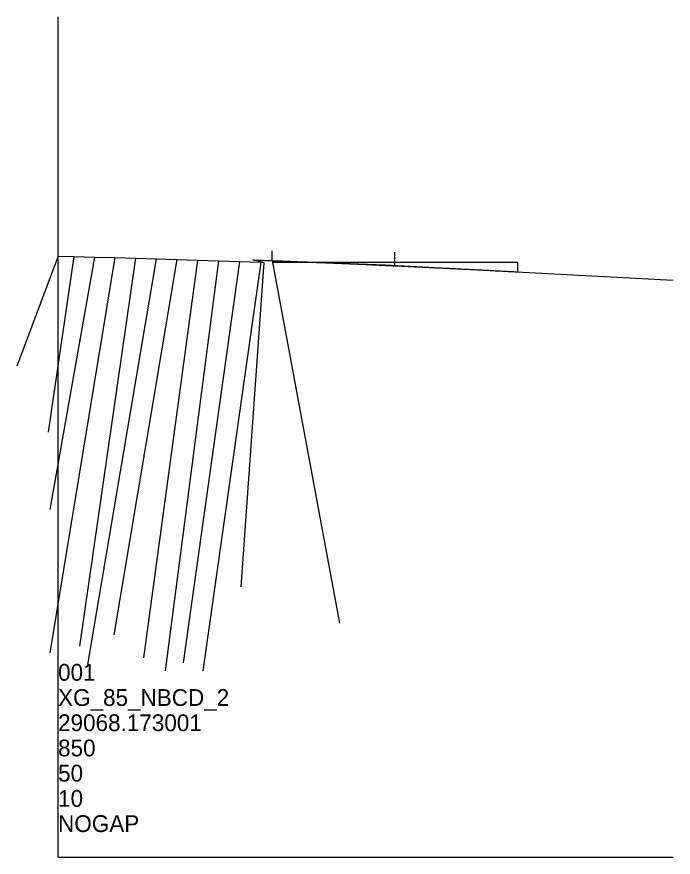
# Model space of a CAD drawing. Extents: x -26 to 1615432, y -20 to 1281970.
# Drawn here: x 176487 to 177268, y 177863 to 178863 of the extents above; entities that cross this region are included whole.
import ezdxf

# ---------------------------------------------------------------- set-up
doc = ezdxf.new("R2010")
doc.units = 0
doc.layers.add('RD_GPK_Profile_Cell', color=7, linetype='Continuous')
doc.layers.add('RD_PD_EarthShd', color=7, linetype='Continuous')

msp = doc.modelspace()

# ---------------------------------------------------------------- linework, layer by layer
at = {"layer": 'RD_GPK_Profile_Cell'}
for q in [(176535.7, 178863), (177267.5, 177863), (176535.7, 177863)]:
    msp.add_line((176535.7, 177863), q, dxfattribs=at)
at = {"layer": 'RD_PD_EarthShd'}
for p, q in [((176790.6, 178572.9), (176790.6, 178584.6)), ((176936.5, 178567.4), (176936.5, 178582.9)), ((176535.7, 178578.3), (176486.6, 178447.3)), ((176554.4, 178577.9), (176523.9, 178368.9)), ((176578.9, 178577.2), (176525.8, 178276.8)), ((176603.4, 178576.6), (176525.8, 178106.2)), ((176627.8, 178575.9), (176561.1, 178114)), ((176652.3, 178575.2), (176570.9, 178092.4)), ((176676.9, 178574.4), (176602.2, 178127.7)), ((176701.6, 178573.6), (176637.5, 178100.3)), ((176726.6, 178572.8), (176663, 178084.6)), ((176751.7, 178571.9), (176684.5, 178094.4)), ((176776.8, 178571), (176708, 178084.6)), ((176780.6, 178570.8), (176753.1, 178184.6)), ((176790.6, 178572.9), (176870.7, 178141.5)), ((176790.6, 178571.2), (177082.5, 178571.2)), ((177082.5, 178559.5), (177082.5, 178571.2))]:
    msp.add_line(p, q, dxfattribs=at)
msp.add_lwpolyline([(176535.7, 178578.3), (176554.4, 178577.9), (176578.9, 178577.2), (176603.4, 178576.6), (176627.8, 178575.9), (176652.3, 178575.2), (176676.9, 178574.4), (176701.6, 178573.6), (176726.6, 178572.8), (176751.7, 178571.9), (176776.8, 178571), (176780.6, 178570.8), (176767.5, 178573.7), (176925, 178568), (177267.5, 178549.5)], dxfattribs=at)
msp.add_spline([(176767.5, 178573.7), (176770.7, 178573.6), (176773.8, 178573.5), (176777, 178573.4), (176780.1, 178573.3), (176783.3, 178573.2), (176786.4, 178573.1), (176789.6, 178572.9), (176792.7, 178572.8), (176795.9, 178572.7), (176799, 178572.6), (176802.2, 178572.5), (176805.3, 178572.3), (176808.5, 178572.2), (176811.6, 178572.1), (176814.8, 178572), (176817.9, 178571.8), (176821.1, 178571.7), (176824.2, 178571.6), (176827.4, 178571.5), (176830.5, 178571.4), (176833.7, 178571.2), (176836.8, 178571.1), (176840, 178571), (176843.1, 178570.8), (176846.3, 178570.7), (176849.4, 178570.6), (176852.6, 178570.5), (176855.7, 178570.3), (176858.9, 178570.2), (176862, 178570.1), (176865.2, 178569.9), (176868.3, 178569.8), (176871.5, 178569.7), (176874.6, 178569.5), (176877.8, 178569.4), (176880.9, 178569.3), (176884.1, 178569.1), (176887.2, 178569), (176890.4, 178568.9), (176893.5, 178568.7), (176896.7, 178568.6), (176899.8, 178568.5), (176903, 178568.3), (176906.1, 178568.2), (176909.3, 178568), (176912.4, 178567.9), (176915.6, 178567.8), (176918.7, 178567.6), (176921.9, 178567.5), (176925, 178567.3), (176928.2, 178567.2), (176931.3, 178567.1), (176934.5, 178566.9), (176937.6, 178566.8), (176940.8, 178566.6), (176943.9, 178566.5), (176947.1, 178566.3), (176950.2, 178566.2), (176953.4, 178566), (176956.5, 178565.9), (176959.7, 178565.7), (176962.8, 178565.6), (176966, 178565.4), (176969.1, 178565.3), (176972.3, 178565.1), (176975.4, 178565), (176978.6, 178564.8), (176981.7, 178564.7), (176984.9, 178564.5), (176988, 178564.4), (176991.2, 178564.2), (176994.3, 178564.1), (176997.5, 178563.9), (177000.6, 178563.8), (177003.8, 178563.6), (177006.9, 178563.5), (177010.1, 178563.3), (177013.2, 178563.1), (177016.4, 178563), (177019.5, 178562.8), (177022.7, 178562.7), (177025.8, 178562.5), (177029, 178562.3), (177032.1, 178562.2), (177035.3, 178562), (177038.4, 178561.9), (177041.6, 178561.7), (177044.7, 178561.5), (177047.9, 178561.4), (177051, 178561.2), (177054.2, 178561), (177057.3, 178560.9), (177060.5, 178560.7), (177063.6, 178560.5), (177066.8, 178560.4), (177069.9, 178560.2), (177073.1, 178560), (177076.2, 178559.9), (177079.4, 178559.7), (177082.5, 178559.5)], degree=3, dxfattribs=at)

# ---------------------------------------------------------------- texts
at = {"layer": 'RD_GPK_Profile_Cell'}
for s, p in [('001', (176535.7, 178073)), ('XG_85_NBCD_2', (176535.7, 178043)), ('29068.173001', (176535.7, 178013)), ('850', (176535.7, 177983)), ('50', (176535.7, 177953)), ('10', (176535.7, 177923)), ('NOGAP', (176535.7, 177893))]:
    msp.add_text(s, height=20, dxfattribs=at).set_placement(p)

doc.saveas('drawing.dxf')
